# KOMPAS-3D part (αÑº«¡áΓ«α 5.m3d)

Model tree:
1. Эскиз:1
2. Операция выдавливания:1
     Толщина стенки 1 = 2; Толщина стенки 2 = 8; Расстояние 1 = 1
3. Эскиз:3
4. Операция выдавливания:2
     Толщина стенки 1 = 2; Толщина стенки 2 = 6; Расстояние 1 = 5.5
5. Эскиз:4
6. Операция выдавливания:3
     Толщина стенки 1 = 2; Толщина стенки 2 = 6; Расстояние 1 = 1
7. Эскиз:5
8. Эскиз:6
9. Операция выдавливания:4
     Толщина стенки 1 = 2; Толщина стенки 2 = 2.5; Расстояние 1 = 50
10. Эскиз:7
11. Вырезать элемент выдавливания:1
     Толщина стенки 2 = 1.5; Расстояние 1 = 40
12. Эскиз:8
13. Операция выдавливания:5
     Толщина стенки 1 = 2; Толщина стенки 2 = 2.5; Расстояние 1 = 50
14. Эскиз:9
15. Вырезать элемент выдавливания:2
     Толщина стенки 2 = 1.5; Расстояние 1 = 40
16. Эскиз:10
17. Операция выдавливания:6
     Толщина стенки 1 = 2; Толщина стенки 2 = 2.5; Расстояние 1 = 10
18. Эскиз:11
19. Операция выдавливания:7
     Толщина стенки 1 = 2; Толщина стенки 2 = 6; Расстояние 1 = 1
20. Эскиз:12
21. Операция выдавливания:8
     Толщина стенки 1 = 2; Толщина стенки 2 = 6; Расстояние 1 = 5.5
22. Эскиз:13
23. Операция выдавливания:9
     Толщина стенки 1 = 2; Толщина стенки 2 = 8; Расстояние 1 = 1
24. Эскиз:14
25. Вырезать элемент выдавливания:3
     Толщина стенки 2 = 1.5; Расстояние 1 = 23
26. Эскиз:15
27. Вырезать элемент выдавливания:4
     Толщина стенки 2 = 1.5; Расстояние 1 = 1
28. Эскиз:16
29. Вырезать элемент выдавливания:5
     Расстояние 1 = 150
30. Эскиз:17
31. Операция выдавливания:10
     Толщина стенки 1 = 8; Расстояние 1 = 10; Расстояние 2 = 0.4
